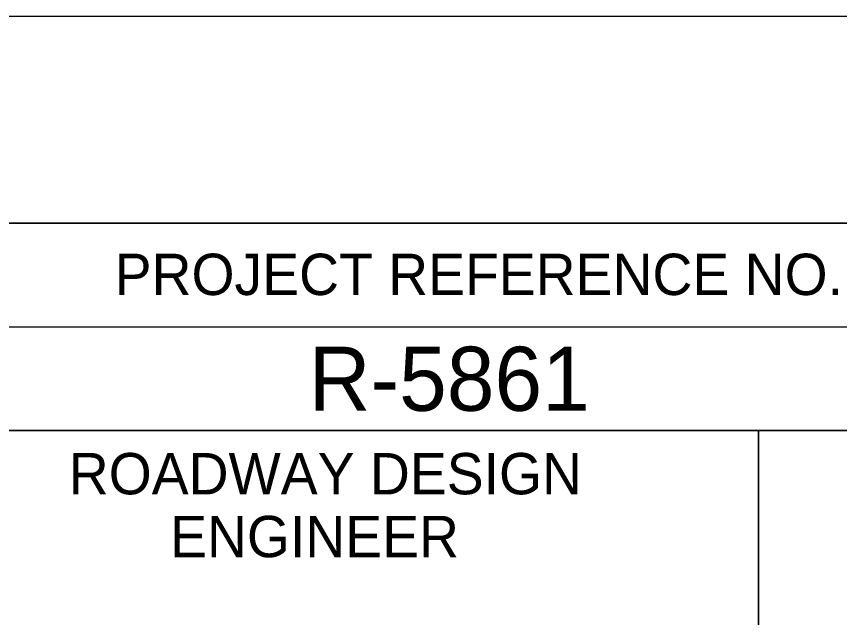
# Model space of a CAD drawing. Extents: x 505602 to 507705, y 483109 to 484209.
# Drawn here: x 507079.4 to 507178.9, y 484136 to 484208.7 of the extents above; entities that cross this region are included whole.
import ezdxf

# ---------------------------------------------------------------- set-up
doc = ezdxf.new("R2010")
doc.units = 0
for name, color, linetype in [('Sheet Data Field CELL', 7, 'Continuous'), ('Sheet Plot Border Outside CELL', 7, 'Continuous'), ('Sheet Profile CELL', 7, 'Continuous'), ('Sheet Profile Grid Major CELL', 7, 'Continuous')]:
    doc.layers.add(name, color=color, linetype=linetype)

msp = doc.modelspace()

# ---------------------------------------------------------------- linework, layer by layer
at = {"layer": 'Sheet Plot Border Outside CELL'}
msp.add_lwpolyline([(505602.08, 483108.712), (507286.08, 483108.712), (507286.08, 484208.712), (505602.08, 484208.712)], close=True, dxfattribs=at)
at = {"layer": 'Sheet Profile CELL'}
for p, q in [((507069.03, 484171.162), (507269.08, 484171.162)), ((507169.08, 484158.662), (507169.08, 484046.212))]:
    msp.add_line(p, q, dxfattribs=at)
for points in [[(507269.08, 484183.712), (505769.08, 484183.712), (505769.08, 483133.712), (507269.08, 483133.712)], [(507069.03, 484183.712), (507269.08, 484183.712), (507269.08, 484158.662), (507069.03, 484158.662)], [(507069.03, 484158.662), (507169.08, 484158.662), (507169.08, 484046.162), (507069.03, 484046.162)], [(507169.08, 484158.662), (507269.08, 484158.662), (507269.08, 484046.162), (507169.08, 484046.162)]]:
    msp.add_lwpolyline(points, close=True, dxfattribs=at)
at = {"layer": 'Sheet Profile Grid Major CELL'}
msp.add_lwpolyline([(506669.08, 484183.712), (506719.08, 484183.712), (506719.08, 483683.712), (506769.08, 483683.712), (506769.08, 484183.712), (506819.08, 484183.712), (506819.08, 483683.712), (506869.08, 483683.712), (506869.08, 484183.712), (506919.08, 484183.712), (506919.08, 483683.712), (506969.08, 483683.712), (506969.08, 484183.712), (507019.08, 484183.712), (507019.08, 483683.712), (507069.08, 483683.712), (507069.08, 484183.712), (507095.38, 484183.712)], dxfattribs=at)

# ---------------------------------------------------------------- texts
at = {"layer": 'Sheet Data Field CELL'}
msp.add_text('R-5861', height=7.7499, dxfattribs=at).set_placement((507114.695, 484161.024))
at = {"layer": 'Sheet Profile CELL'}
for s, p in [('PROJECT REFERENCE NO.', (507091.242, 484175.024)), ('ROADWAY DESIGN', (507085.692, 484150.924)), ('ENGINEER', (507097.942, 484143.324))]:
    msp.add_text(s, height=5.0001, dxfattribs=at).set_placement(p)

doc.saveas('drawing.dxf')
